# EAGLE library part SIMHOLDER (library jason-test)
SIM holder with switch
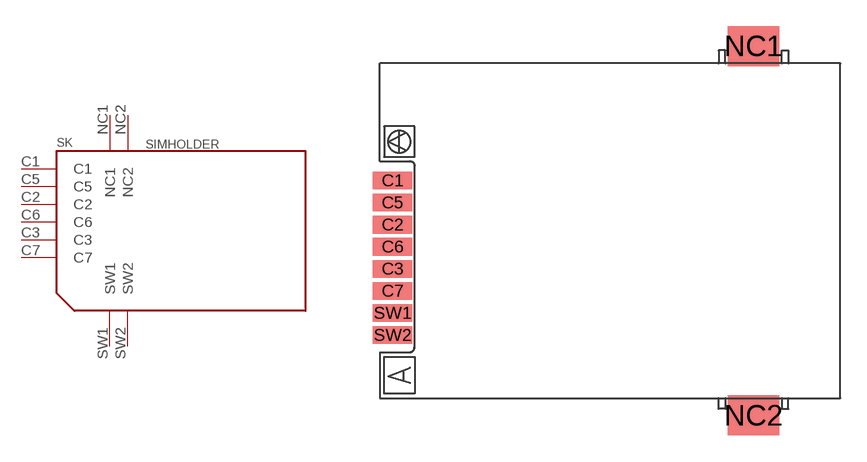
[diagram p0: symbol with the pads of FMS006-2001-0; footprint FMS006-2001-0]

Designator prefix SK

## SIMHOLDER  [FMS006-2001-0]
C1  C1  pwr
C2  C2  in
C3  C3  in
C5  C5  pwr
C6  C6  nc
C7  C7
NC1  NC1  nc
NC2  NC2  nc
SW1  SW1
SW2  SW2

## Footprint FMS006-2001-0 (pad centres in mm)
FMS006-2001-0 SIM socket (with switch)
smd 2.286 x 1.016: C1 0,0.096; C2 0,-2.444; C3 0,-4.984; C5 0,-1.174; C6 0,-3.714; C7 0,-6.254; SW1 0,-7.524; SW2 0,-8.794
smd 2.95 x 2.3: NC1 20.77,7.831; NC2 20.77,-13.419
